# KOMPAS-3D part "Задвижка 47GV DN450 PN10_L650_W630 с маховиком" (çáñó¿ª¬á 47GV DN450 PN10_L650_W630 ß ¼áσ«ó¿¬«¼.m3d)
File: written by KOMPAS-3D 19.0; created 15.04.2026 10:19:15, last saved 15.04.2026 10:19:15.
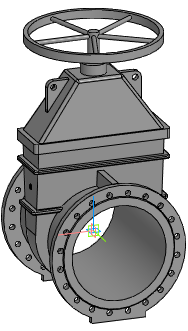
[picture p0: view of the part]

Document properties: Автор: Евгений; Полное имя файла: Z:\3.Личные\kachalov\3d для проектировщиков\2.1 Тип 47GV, 47GV.Z\Задвижка 47GV_DN40-DN600\stp_Задвижка 47GV\Задвижка 47GV DN450 PN10_L650_W630 с маховиком.m3d

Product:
- Part/product: Задвижка 47GV DN450 PN10_L650_W630 с маховиком

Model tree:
1. Операция без истории:1  (labels: Задвижка 47GV DN450 PN10_L650_W630 с маховиком)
